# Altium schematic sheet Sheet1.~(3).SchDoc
size A3
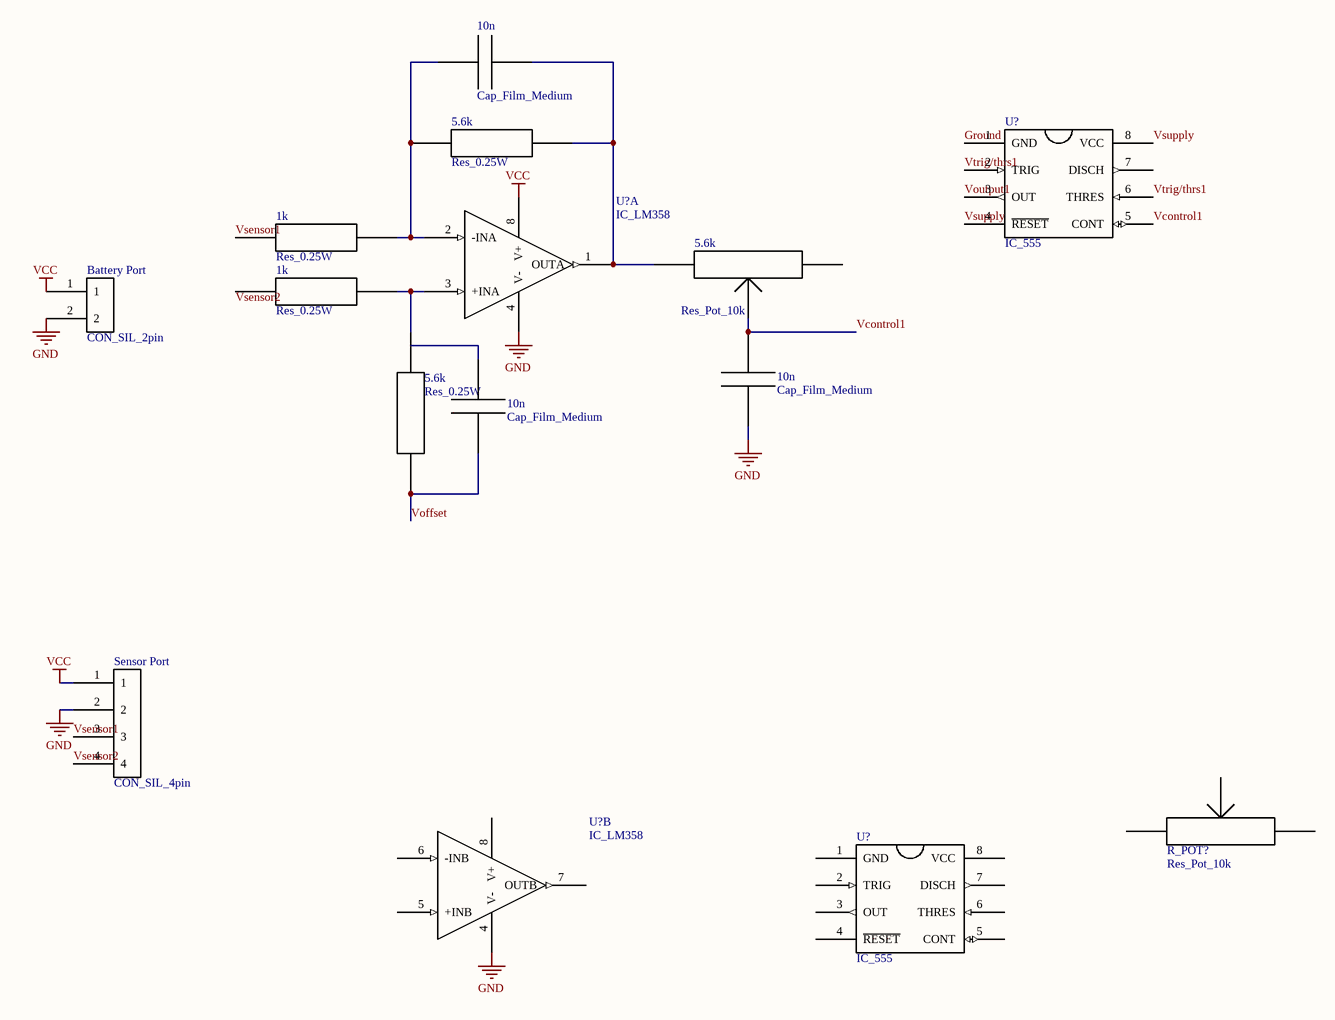
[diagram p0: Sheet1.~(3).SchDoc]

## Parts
(Parts that share a designator on the sheet are numbered #1, #2 ... from top to bottom, then left to right.)
1k#1  Res_0.25W  [Resistor_400mil_pitch]
1k#2  Res_0.25W  [Resistor_400mil_pitch]
5.6k#1  Res_0.25W  [Resistor_400mil_pitch]
5.6k#2  Res_Pot_10k  [POT]
5.6k#3  Res_0.25W  [Resistor_400mil_pitch]
10n#1  Cap_Film_Medium  [CAP_FILM_3.2mm]
10n#2  Cap_Film_Medium  [CAP_FILM_3.2mm]
10n#3  Cap_Film_Medium  [CAP_FILM_3.2mm]
Battery_Port  CON_SIL_2pin  [ece-HDR1X2]
R_POT?  Res_Pot_10k  [POT]
Sensor_Port  CON_SIL_4pin  [ece-HDR1X4]
U?#1  IC_555  [DIP_8]
U?#2  IC_LM358  [DIP_8]  (part A of 2)
U?#3  IC_LM358  [DIP_8]  (part B of 2)
U?#4  IC_555  [DIP_8]

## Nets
GND: 10n#2.2 Battery_Port.2 Sensor_Port.2 U?#2.4(V-) U?#3.4(V-)
VCC: Battery_Port.1 Sensor_Port.1 U?#2.8(V+)
Ground: U?#1.1(GND)
Vcontrol1: 5.6k#2.2 10n#2.1 U?#1.5(CONT)
Voffset: 5.6k#3.1 10n#3.1
Voutput1: U?#1.3(OUT)
Vsensor1: 1k#1.1 Sensor_Port.3
Vsensor2: Sensor_Port.4
Vsupply: U?#1.4(~{RESET}) U?#1.8(VCC)
Vtrig/thrs1: U?#1.2(TRIG) U?#1.6(THRES)
Net1k#1_2: 1k#1.2 5.6k#1.1 10n#1.1 U?#2.2(-INA)
Net1k#2_2: 1k#2.2 5.6k#3.2 U?#2.3(+INA)
Net5.6k#1_2: 5.6k#1.2 5.6k#2.3 10n#1.2 U?#2.1(OUTA)

Not connected (* = marked no-connect by the designer): 1k#2 1; 5.6k#2 1; 10n#3 2; R_POT? 1 2 3; U?#1 7(DISCH); U?#3 5(+INB) 6(-INB) 7(OUTB) 8(V+); U?#4 1(GND) 2(TRIG) 3(OUT) 4(~{RESET}) 5(CONT) 6(THRES) 7(DISCH) 8(VCC)

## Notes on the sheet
- Labels drawn without touching a wire or pin: Vsensor2

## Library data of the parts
10n#1-10n#3 = Cap_Film_Medium: Cap_Ceramic
Battery_Port = CON_SIL_2pin: 2 pin in line connector
Sensor_Port = CON_SIL_4pin: 4 pin in line connector
U?#1 U?#4 = IC_555: NEC555
U?#2 U?#3 = IC_LM358: LM358 - Dual Opamp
